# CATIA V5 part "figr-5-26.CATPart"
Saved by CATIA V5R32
Part number: Part1
Bounding box of the stored display mesh (mm): x -75 to 75, y -100 to 100, z 0 to 53
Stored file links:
  D:\PROJECTS\Project 2022\CATIA V5 6R 2022\Resources\Part Files\c05_catia_v5_6r2022_prt\figr-5-26.CATPart
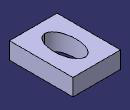
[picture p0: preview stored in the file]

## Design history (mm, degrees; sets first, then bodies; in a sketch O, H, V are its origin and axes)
Body1 (main body)
  Sketch1 on xy-plane, origin (0, 0, 0), H (1, 0, 0), V (0, 1, 0)
    line L1 (-75, 100) -> (75, 100)
    line L2 (75, 100) -> (75, -100)
    line L3 (75, -100) -> (-75, -100)
    line L4 (-75, -100) -> (-75, 100)
    axis line L5 (75, -100) -> (-75, 100)
    length L3 = 150
    length L2 = 200
    horizontal: L1 H, L3 H
    vertical: L2 V, L4 V
    midpoint: L5 O
  Pad1: profile Sketch1, direction (0, 0, 1), length 53
  Sketch2 on face of Pad1, origin (0, 0, 53), H (1, 0, 0), V (0, 1, 0)
    ellipse A1 centre (0, 0) semi-axes 63.781, 34.5424 rotation 270
    point P1 (0, -63.781)
    point P2 (34.5424, 0)
    coincidence: P1 V, P2 H, A1 P1, A1 P2
  Pocket1: profile Sketch2, direction (0, 0, -1), through (limit type 3)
